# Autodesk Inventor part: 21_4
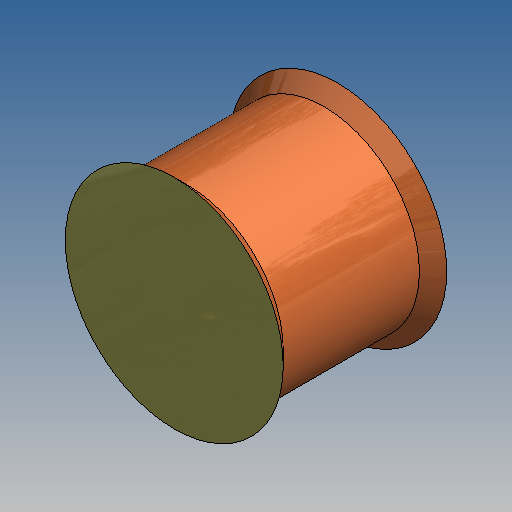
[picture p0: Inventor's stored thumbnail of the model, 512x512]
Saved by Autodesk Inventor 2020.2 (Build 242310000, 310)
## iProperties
Part Number: 21_4
Material: Generic
Document SubType Name: Modeling
Designer: amoles
Appearance: Default
Author: amoles
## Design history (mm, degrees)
feature "Base1"
body "Solid1"
